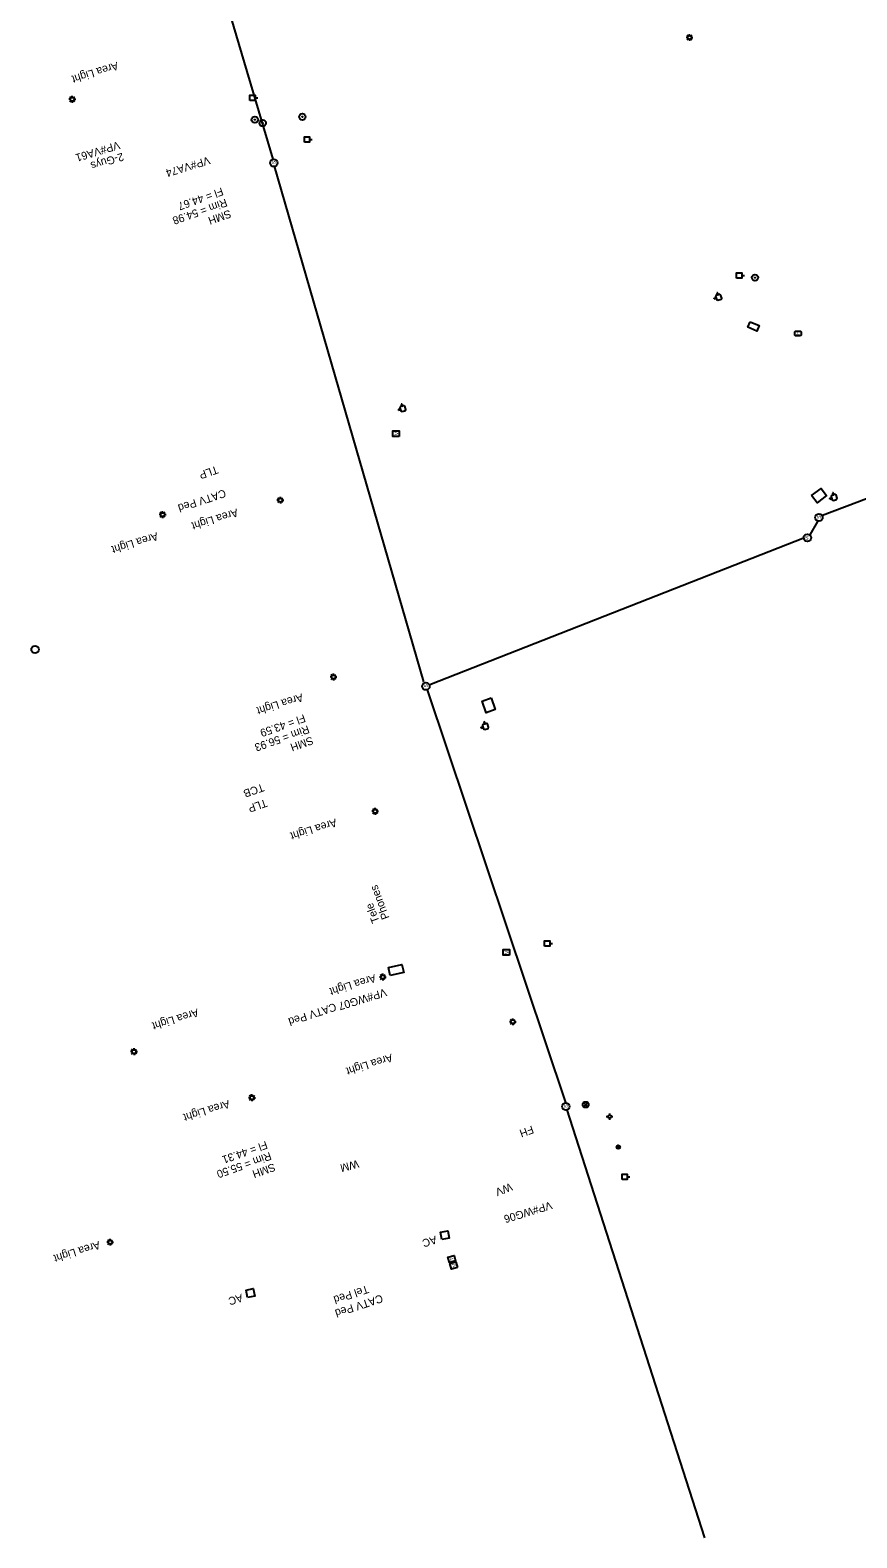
# Model space of a CAD drawing. Extents: x 3872070 to 3879223, y 293944 to 310567.
# Drawn here: x 3874719 to 3875034, y 305428 to 306002 of the extents above; entities that cross this region are included whole.
import ezdxf

# ---------------------------------------------------------------- set-up
doc = ezdxf.new("R2010")
doc.units = 0
for name, color, linetype in [('Level 11', 7, 'Continuous'), ('Level 3', 7, 'Continuous'), ('Level 33', 7, 'Continuous'), ('Level 34', 7, 'Continuous'), ('Level 35', 7, 'Continuous'), ('Level 37', 7, 'Continuous'), ('Level 38', 7, 'Continuous'), ('Level 39', 7, 'Continuous'), ('Level 4', 7, 'Continuous'), ('Level 5', 7, 'Continuous'), ('Level 7', 7, 'Continuous'), ('Level 8', 7, 'Continuous'), ('Level 9', 7, 'Continuous')]:
    doc.layers.add(name, color=color, linetype=linetype)

msp = doc.modelspace()

# ---------------------------------------------------------------- linework, layer by layer
at = {"layer": 'Level 11'}
msp.add_circle((3874720.56, 305766.47), 1.41, dxfattribs=at)
at = {"layer": 'Level 3'}
for p, q in [((3874811.26, 305953.3), (3874718.68, 306265.62)), ((3874868.74, 305754.21), (3874811.83, 305950.54)), ((3875174.8, 305876.27), (3875020.61, 305817.48)), ((3875018.69, 305815.26), (3875015.81, 305810.22)), ((3875013.71, 305808.97), (3874870.99, 305753.08)), ((3874922.78, 305593.92), (3874870.03, 305751.07)), ((3874975.78, 305428.13), (3874923.23, 305591.55))]:
    msp.add_line(p, q, dxfattribs=at)
for points in [[(3874875.59, 305541.73), (3874875.03, 305544.55), (3874877.79, 305545.11), (3874878.36, 305542.29)], [(3874801.51, 305519.67), (3874800.94, 305522.49), (3874803.71, 305523.05), (3874804.27, 305520.23)]]:
    msp.add_lwpolyline(points, close=True, dxfattribs=at)
for centre in [(3874811.53, 305951.81), (3875019.24, 305816.75), (3875014.84, 305809.04), (3874869.49, 305752.47), (3874922.81, 305592.4)]:
    msp.add_circle(centre, 1.41, dxfattribs=at)
at = {"layer": 'Level 4'}
for p, q in [((3874969.22, 305999.61), (3874968.65, 305999.61)), ((3874969.43, 306000.13), (3874969.03, 306000.53)), ((3874969.95, 306000.34), (3874969.95, 306000.91)), ((3874970.46, 306000.13), (3874970.87, 306000.53)), ((3874970.67, 305999.61), (3874971.25, 305999.61)), ((3874969.03, 305998.7), (3874969.43, 305999.1)), ((3874969.95, 305998.89), (3874969.95, 305998.31)), ((3874970.87, 305998.7), (3874970.46, 305999.1)), ((3874734.23, 305976.57), (3874733.82, 305976.98)), ((3874734.74, 305976.79), (3874734.74, 305977.36)), ((3874735.26, 305976.57), (3874735.66, 305976.98)), ((3874804.41, 305976.65), (3874805.41, 305976.65)), ((3874734.02, 305976.06), (3874733.44, 305976.06)), ((3874733.82, 305975.14), (3874734.23, 305975.55)), ((3874734.74, 305975.34), (3874734.74, 305974.76)), ((3874735.66, 305975.14), (3874735.26, 305975.55)), ((3874735.47, 305976.06), (3874736.04, 305976.06)), ((3874825.18, 305960.69), (3874826.18, 305960.69)), ((3874989.88, 305908.9), (3874990.88, 305908.9)), ((3874813.29, 305823.34), (3874812.72, 305823.34)), ((3874813.51, 305823.85), (3874813.1, 305824.26)), ((3874813.1, 305822.42), (3874813.51, 305822.83)), ((3874814.02, 305824.07), (3874814.02, 305824.64)), ((3874814.02, 305822.62), (3874814.02, 305822.04)), ((3874814.53, 305823.85), (3874814.94, 305824.26)), ((3874814.94, 305822.42), (3874814.53, 305822.83)), ((3874814.74, 305823.34), (3874815.32, 305823.34)), ((3874768.43, 305817.87), (3874767.85, 305817.87)), ((3874768.64, 305818.38), (3874768.23, 305818.79)), ((3874768.23, 305816.95), (3874768.64, 305817.35)), ((3874769.15, 305818.59), (3874769.15, 305819.17)), ((3874769.15, 305817.14), (3874769.15, 305816.57)), ((3874769.67, 305818.38), (3874770.07, 305818.79)), ((3874770.07, 305816.95), (3874769.67, 305817.35)), ((3874769.88, 305817.87), (3874770.45, 305817.87)), ((3874833.55, 305756.04), (3874832.97, 305756.04)), ((3874833.76, 305756.55), (3874833.35, 305756.96)), ((3874833.35, 305755.12), (3874833.76, 305755.53)), ((3874834.27, 305756.76), (3874834.27, 305757.34)), ((3874834.27, 305755.31), (3874834.27, 305754.74)), ((3874834.79, 305756.55), (3874835.19, 305756.96)), ((3874835.19, 305755.12), (3874834.79, 305755.53)), ((3874835, 305756.04), (3874835.57, 305756.04)), ((3874849.42, 305704.86), (3874848.85, 305704.86)), ((3874849.63, 305705.38), (3874849.23, 305705.78)), ((3874849.23, 305703.94), (3874849.63, 305704.35)), ((3874850.15, 305705.59), (3874850.15, 305706.16)), ((3874850.15, 305704.14), (3874850.15, 305703.56)), ((3874850.66, 305705.38), (3874851.06, 305705.78)), ((3874851.06, 305703.94), (3874850.66, 305704.35)), ((3874850.87, 305704.86), (3874851.45, 305704.86)), ((3874916.67, 305654.52), (3874917.67, 305654.52)), ((3874852.31, 305641.73), (3874851.74, 305641.73)), ((3874852.52, 305642.24), (3874852.12, 305642.65)), ((3874852.12, 305640.81), (3874852.52, 305641.22)), ((3874853.04, 305642.46), (3874853.04, 305643.03)), ((3874853.04, 305641.01), (3874853.04, 305640.43)), ((3874853.55, 305642.24), (3874853.96, 305642.65)), ((3874853.96, 305640.81), (3874853.55, 305641.22)), ((3874853.76, 305641.73), (3874854.34, 305641.73)), ((3874902.61, 305625.43), (3874902.61, 305626)), ((3874901.88, 305624.7), (3874901.31, 305624.7)), ((3874902.1, 305625.21), (3874901.69, 305625.62)), ((3874901.69, 305623.78), (3874902.1, 305624.19)), ((3874902.61, 305623.98), (3874902.61, 305623.4)), ((3874903.12, 305625.21), (3874903.53, 305625.62)), ((3874903.53, 305623.78), (3874903.12, 305624.19)), ((3874903.33, 305624.7), (3874903.91, 305624.7)), ((3874758.28, 305614.04), (3874758.28, 305614.61)), ((3874757.56, 305613.31), (3874756.98, 305613.31)), ((3874757.77, 305613.83), (3874757.36, 305614.23)), ((3874757.36, 305612.39), (3874757.77, 305612.8)), ((3874758.28, 305612.59), (3874758.28, 305612.01)), ((3874758.8, 305613.83), (3874759.2, 305614.23)), ((3874759.2, 305612.39), (3874758.8, 305612.8)), ((3874759.01, 305613.31), (3874759.58, 305613.31)), ((3874802.49, 305595.77), (3874801.92, 305595.77)), ((3874802.7, 305596.28), (3874802.3, 305596.68)), ((3874802.3, 305594.85), (3874802.7, 305595.25)), ((3874803.21, 305596.49), (3874803.21, 305597.07)), ((3874803.21, 305595.04), (3874803.21, 305594.47)), ((3874803.73, 305596.28), (3874804.13, 305596.68)), ((3874804.13, 305594.85), (3874803.73, 305595.25)), ((3874803.94, 305595.77), (3874804.52, 305595.77)), ((3874946.2, 305565.66), (3874947.2, 305565.66)), ((3874748.47, 305540.77), (3874747.9, 305540.77)), ((3874748.68, 305541.28), (3874748.28, 305541.69)), ((3874748.28, 305539.85), (3874748.68, 305540.26)), ((3874749.2, 305541.49), (3874749.2, 305542.07)), ((3874749.2, 305540.04), (3874749.2, 305539.47)), ((3874749.71, 305541.28), (3874750.12, 305541.69)), ((3874750.12, 305539.85), (3874749.71, 305540.26)), ((3874749.92, 305540.77), (3874750.5, 305540.77))]:
    msp.add_line(p, q, dxfattribs=at)
for points in [[(3874802.41, 305975.65), (3874802.41, 305977.65), (3874804.41, 305977.65), (3874804.41, 305975.65)], [(3874823.18, 305959.69), (3874823.18, 305961.69), (3874825.18, 305961.69), (3874825.18, 305959.69)], [(3874987.88, 305907.9), (3874987.88, 305909.9), (3874989.88, 305909.9), (3874989.88, 305907.9)], [(3874914.67, 305653.52), (3874914.67, 305655.52), (3874916.67, 305655.52), (3874916.67, 305653.52)], [(3874944.2, 305564.66), (3874944.2, 305566.66), (3874946.2, 305566.66), (3874946.2, 305564.66)]]:
    msp.add_lwpolyline(points, close=True, dxfattribs=at)
for centre, radius in [((3874969.95, 305999.61), 0.725), ((3874734.74, 305976.06), 0.725), ((3874822.41, 305969.38), 1.22), ((3874804.3, 305968.28), 1.22), ((3874804.3, 305968.28), 0.0992), ((3874804.3, 305968.28), 0.0483), ((3874807.3, 305966.99), 1.22), ((3874807.3, 305966.99), 0.0992), ((3874807.3, 305966.99), 0.0483), ((3874822.41, 305969.38), 0.0992), ((3874822.41, 305969.38), 0.0483), ((3874994.86, 305908.12), 1.22), ((3874994.86, 305908.12), 0.0992), ((3874994.86, 305908.12), 0.0483), ((3874814.02, 305823.34), 0.725), ((3874769.15, 305817.87), 0.725), ((3874834.27, 305756.04), 0.725), ((3874850.15, 305704.86), 0.725), ((3874853.04, 305641.73), 0.725), ((3874902.61, 305624.7), 0.725), ((3874758.28, 305613.31), 0.725), ((3874803.21, 305595.77), 0.725), ((3874749.2, 305540.77), 0.725)]:
    msp.add_circle(centre, radius, dxfattribs=at)
at = {"layer": 'Level 5'}
for p, q in [((3874929.56, 305593.91), (3874930.36, 305593.11)), ((3874929.56, 305592.32), (3874930.36, 305593.11)), ((3874931.15, 305593.91), (3874930.36, 305593.11)), ((3874931.15, 305592.32), (3874930.36, 305593.11)), ((3874938.22, 305588.55), (3874938.85, 305588.55)), ((3874939.47, 305589.8), (3874939.47, 305589.17)), ((3874939.47, 305587.93), (3874939.47, 305587.3)), ((3874940.09, 305588.55), (3874940.72, 305588.55)), ((3874941.93, 305576.96), (3874942.29, 305576.96)), ((3874942.29, 305576.96), (3874943.29, 305576.96)), ((3874943.29, 305576.96), (3874943.65, 305576.96))]:
    msp.add_line(p, q, dxfattribs=at)
for centre, radius in [((3874930.36, 305593.11), 1.12), ((3874939.47, 305588.55), 0.625), ((3874942.79, 305576.96), 0.7)]:
    msp.add_circle(centre, radius, dxfattribs=at)
msp.add_arc((3874942.79, 305576.96), 0.5, 0, 180, dxfattribs=at)
at = {"layer": 'Level 7'}
for points in [[(3874855.89, 305642.29), (3874855.2, 305645.33), (3874860.35, 305646.5), (3874861.04, 305643.46)], [(3874880.79, 305533.63), (3874878.49, 305532.98), (3874877.89, 305535.08), (3874880.2, 305535.73)]]:
    msp.add_lwpolyline(points, close=True, dxfattribs=at)
at = {"layer": 'Level 8'}
for points in [[(3874859.34, 305847.64), (3874856.94, 305847.64), (3874856.94, 305849.83), (3874859.34, 305849.83)], [(3874901.32, 305650.02), (3874898.92, 305650.02), (3874898.92, 305652.21), (3874901.32, 305652.21)], [(3874881.56, 305531.13), (3874879.26, 305530.46), (3874878.64, 305532.56), (3874880.94, 305533.23)]]:
    msp.add_lwpolyline(points, close=True, dxfattribs=at)
at = {"layer": 'Level 9'}
for p, q in [((3874980.04, 305900.46), (3874979.3, 305900.23)), ((3874979.37, 305899.99), (3874979.3, 305900.23)), ((3874980.11, 305900.22), (3874979.37, 305899.99)), ((3874859.74, 305858.07), (3874859, 305857.84)), ((3874859.08, 305857.59), (3874859, 305857.83)), ((3874859.82, 305857.83), (3874859.08, 305857.6)), ((3875024.08, 305824.26), (3875023.34, 305824.03)), ((3875023.41, 305823.79), (3875023.34, 305824.03)), ((3875024.15, 305824.03), (3875023.41, 305823.79)), ((3874891.24, 305737.03), (3874890.5, 305736.8)), ((3874890.57, 305736.56), (3874890.5, 305736.8)), ((3874891.31, 305736.8), (3874890.57, 305736.56))]:
    msp.add_line(p, q, dxfattribs=at)
for points in [[(3874980.71, 305899.49), (3874981.95, 305899.88), (3874982.18, 305900.32), (3874981.79, 305901.56), (3874981.35, 305901.79), (3874980.12, 305901.4), (3874979.88, 305900.96), (3874980.27, 305899.72)], [(3874980.38, 305902.3), (3874980.61, 305901.56), (3874980.85, 305901.63), (3874980.62, 305902.38)], [(3874979.37, 305899.99), (3874980.12, 305900.22), (3874980.04, 305900.46), (3874979.3, 305900.23)], [(3875012.16, 305885.96), (3875010.25, 305885.96), (3875010, 305886.21), (3875010, 305887.43), (3875010.25, 305887.68), (3875012.16, 305887.68), (3875012.41, 305887.43), (3875012.41, 305886.21)], [(3874859.08, 305857.59), (3874859.82, 305857.83), (3874859.74, 305858.07), (3874859, 305857.83)], [(3874860.42, 305857.1), (3874861.65, 305857.49), (3874861.88, 305857.93), (3874861.5, 305859.16), (3874861.05, 305859.39), (3874859.82, 305859.01), (3874859.59, 305858.56), (3874859.98, 305857.33)], [(3874860.08, 305859.91), (3874860.32, 305859.16), (3874860.56, 305859.24), (3874860.32, 305859.98)], [(3875023.41, 305823.79), (3875024.16, 305824.02), (3875024.08, 305824.26), (3875023.34, 305824.03)], [(3875024.75, 305823.29), (3875025.99, 305823.68), (3875026.22, 305824.12), (3875025.83, 305825.36), (3875025.39, 305825.59), (3875024.16, 305825.2), (3875023.92, 305824.76), (3875024.31, 305823.53)], [(3875024.42, 305826.1), (3875024.65, 305825.36), (3875024.89, 305825.43), (3875024.66, 305826.18)], [(3874890.57, 305736.56), (3874891.32, 305736.79), (3874891.24, 305737.03), (3874890.5, 305736.8)], [(3874891.92, 305736.06), (3874893.15, 305736.45), (3874893.38, 305736.89), (3874892.99, 305738.13), (3874892.55, 305738.36), (3874891.32, 305737.97), (3874891.08, 305737.53), (3874891.47, 305736.3)], [(3874891.58, 305738.87), (3874891.81, 305738.13), (3874892.05, 305738.2), (3874891.82, 305738.95)]]:
    msp.add_lwpolyline(points, close=True, dxfattribs=at)
for points in [[(3874993.06, 305891.33), (3874996.44, 305889.87), (3874995.53, 305887.76), (3874992.15, 305889.22), (3874993.06, 305891.33)], [(3875016.46, 305825.11), (3875020.06, 305827.84), (3875022.16, 305825.08), (3875018.56, 305822.35), (3875016.46, 305825.11)], [(3874894.3, 305748.04), (3874895.91, 305743.62), (3874892.48, 305742.38), (3874890.87, 305746.79), (3874894.3, 305748.04)]]:
    msp.add_lwpolyline(points, dxfattribs=at)

# ---------------------------------------------------------------- texts
at = {"layer": 'Level 3'}
for rotation, p in [(90, (3874812.24, 305951.33)), (90, (3875019.95, 305816.27)), (180, (3875015.31, 305809.75)), (90, (3874870.2, 305752)), (90, (3874923.52, 305591.92))]:
    msp.add_text('S', height=1.41, rotation=rotation, dxfattribs=at).set_placement(p)
at = {"layer": 'Level 33'}
for s, p in [('Fl = 44.67', (3874791.64, 305942.51)), ('Rim = 54.98', (3874793.13, 305938.27)), ('SMH', (3874794.63, 305934.02)), ('Fl = 43.59', (3874822.95, 305741.88)), ('Rim = 56.93', (3874824.44, 305737.64)), ('SMH', (3874825.94, 305733.4)), ('Rim = 55.50', (3874809.97, 305575.11)), ('Fl = 44.31', (3874808.47, 305579.35)), ('SMH', (3874811.47, 305570.87))]:
    msp.add_text(s, height=3, rotation=199.43656, dxfattribs=at).set_placement(p)
at = {"layer": 'Level 34'}
for s, rotation, p in [('Area Light', 197.24972, (3874751.75, 305990.35)), ('VP#VA61', 196.9281, (3874752.35, 305960.12)), ('2-Guys', 196.9281, (3874753.83, 305955.72)), ('VP#VA74', 196.9281, (3874786.71, 305954.31)), ('Area Light', 197.24972, (3874797.37, 305820.18)), ('Area Light', 197.24972, (3874766.9, 305811.17)), ('Area Light', 197.24972, (3874822.17, 305749.79)), ('Area Light', 197.24972, (3874835, 305702.1)), ('Area Light', 197.24972, (3874849.91, 305642.87)), ('VP#WG07', 196.9281, (3874854, 305637.43)), ('Area Light', 197.24972, (3874782.35, 305629.73)), ('Area Light', 197.24972, (3874856.27, 305612.54)), ('Area Light', 197.24972, (3874794.25, 305594.92)), ('VP#WG06', 196.9281, (3874917.04, 305556.34)), ('Area Light', 197.24972, (3874744.82, 305541.22)), ('AC', 196.9281, (3874873.12, 305543.24)), ('AC', 196.9281, (3874799.23, 305521.14))]:
    msp.add_text(s, height=3, rotation=rotation, dxfattribs=at).set_placement(p)
at = {"layer": 'Level 35'}
for s, rotation, p in [('FH', 199.81479, (3874909.89, 305585.2)), ('WM', 195.02439, (3874843.46, 305572.12)), ('WV', 201.82002, (3874901.63, 305563.39))]:
    msp.add_text(s, height=3, rotation=rotation, dxfattribs=at).set_placement(p)
at = {"layer": 'Level 37'}
for s, rotation, p in [('Phones', 110.39203, (3874855.62, 305664.31)), ('Tele', 110.39203, (3874851.87, 305662.91)), ('Tel Ped', 198.34823, (3874847.12, 305524.38))]:
    msp.add_text(s, height=3, rotation=rotation, dxfattribs=at).set_placement(p)
at = {"layer": 'Level 38'}
for p in [(3874792.7, 305827.56), (3874834.76, 305631.92), (3874852.52, 305520.9)]:
    msp.add_text('CATV Ped', height=3, rotation=198.34823, dxfattribs=at).set_placement(p)
at = {"layer": 'Level 39'}
for s, p in [('TLP', (3874789.7, 305836.53)), ('TCB', (3874807.21, 305715.48)), ('TLP', (3874808.37, 305709.58))]:
    msp.add_text(s, height=3, rotation=199.15116, dxfattribs=at).set_placement(p)
at = {"layer": 'Level 7'}
msp.add_text('T', height=1.41, rotation=105.76317, dxfattribs=at).set_placement((3874880.25, 305534.01))
at = {"layer": 'Level 8'}
for rotation, p in [(90, (3874858.92, 305848.09)), (90, (3874900.89, 305650.47)), (106.34312, (3874881.03, 305531.45))]:
    msp.add_text('V', height=1.41, rotation=rotation, dxfattribs=at).set_placement(p)
at = {"layer": 'Level 9'}
msp.add_text('H', height=1.41, rotation=90, dxfattribs=at).set_placement((3875011.91, 305886.35))

doc.saveas('drawing.dxf')
